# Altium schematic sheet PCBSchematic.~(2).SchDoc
size Letter; SheetNumber: 1; SheetTotal: 1
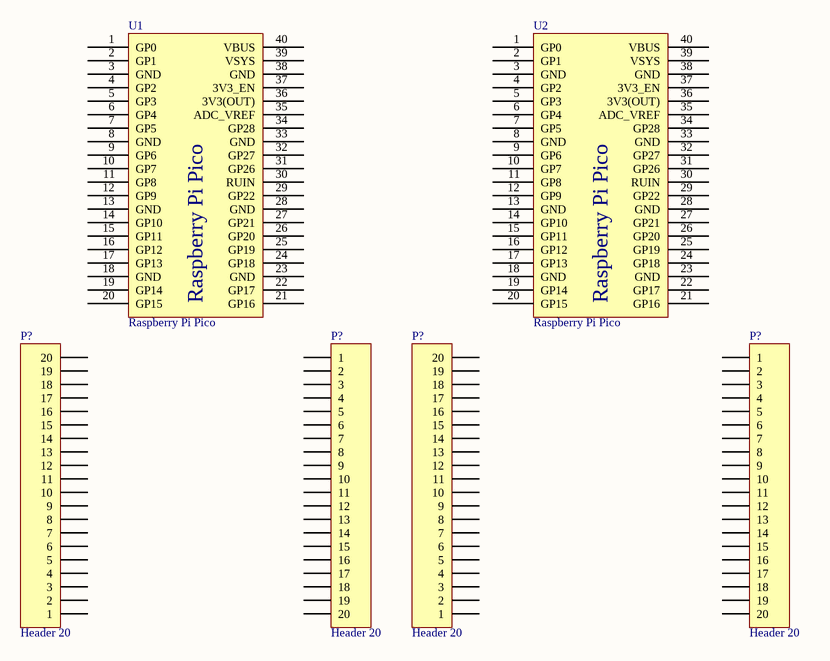
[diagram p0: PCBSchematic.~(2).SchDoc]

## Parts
(Parts that share a designator on the sheet are numbered #1, #2 ... from top to bottom, then left to right.)
P?#1  Header 20  [HDR1X20]
P?#2  Header 20  [HDR1X20]
P?#3  Header 20  [HDR1X20]
P?#4  Header 20  [HDR1X20]
U1  Raspberry Pi Pico  [Raspberry Pi Pico]
U2  Raspberry Pi Pico  [Raspberry Pi Pico]

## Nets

Not connected (* = marked no-connect by the designer): P?#1 1 2 3 4 5 6 7 8 9 10 11 12 13 14 15 16 17 18 19 20; P?#2 1 2 3 4 5 6 7 8 9 10 11 12 13 14 15 16 17 18 19 20; P?#3 1 2 3 4 5 6 7 8 9 10 11 12 13 14 15 16 17 18 19 20; P?#4 1 2 3 4 5 6 7 8 9 10 11 12 13 14 15 16 17 18 19 20; U1 1(GP0) 2(GP1) 3(GND) 4(GP2) 5(GP3) 6(GP4) 7(GP5) 8(GND) 9(GP6) 10(GP7) 11(GP8) 12(GP9) 13(GND) 14(GP10) 15(GP11) 16(GP12) 17(GP13) 18(GND) 19(GP14) 20(GP15) 21(GP16) 22(GP17) 23(GND) 24(GP18) 25(GP19) 26(GP20) 27(GP21) 28(GND) 29(GP22) 30(RUIN) 31(GP26) 32(GP27) 33(GND) 34(GP28) 35(ADC_VREF) 36(3V3(OUT)) 37(3V3_EN) 38(GND) 39(VSYS) 40(VBUS); U2 1(GP0) 2(GP1) 3(GND) 4(GP2) 5(GP3) 6(GP4) 7(GP5) 8(GND) 9(GP6) 10(GP7) 11(GP8) 12(GP9) 13(GND) 14(GP10) 15(GP11) 16(GP12) 17(GP13) 18(GND) 19(GP14) 20(GP15) 21(GP16) 22(GP17) 23(GND) 24(GP18) 25(GP19) 26(GP20) 27(GP21) 28(GND) 29(GP22) 30(RUIN) 31(GP26) 32(GP27) 33(GND) 34(GP28) 35(ADC_VREF) 36(3V3(OUT)) 37(3V3_EN) 38(GND) 39(VSYS) 40(VBUS)

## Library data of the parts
P?#1-P?#4 = Header 20: Header, 20-Pin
